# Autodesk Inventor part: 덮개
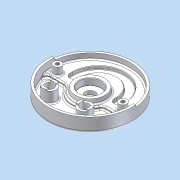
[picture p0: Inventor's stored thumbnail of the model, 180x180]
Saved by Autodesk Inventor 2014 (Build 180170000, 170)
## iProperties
Company: 한국ATC센터
Created: 2015-04
Part Number: 덮개
Document SubType Name: Modeling
Designer: KYOUNG IL JANG
Density: 2.71 g/cm^3
Material: 알루미늄-6061
Appearance: 매끄러움 - 흰색
Author: KYOUNG IL JANG
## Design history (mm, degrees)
sketch "스케치1"
  geometry: L1 (-59, -19)-(-59, 19); L2 (59, 19)-(59, -19); L3 (-41, 19)-(-41, -19); L4 (41, -19)-(41, 19); L5 (59, 5)-(41, 5); L6 (-41, 5)-(-59, 5); C1 r 90 at (0, 0); C2 r 95 at (0, 0); A1 r 59 centre (0, 19) between (59, 19) and (-59, 19); A2 r 59 centre (0, -19) between (-59, -19) and (59, -19); A3 r 41 centre (0, -19) between (-41, -19) and (41, -19); A4 r 41 centre (0, 19) between (41, 19) and (-41, 19); 2 further points
  constraints: 12 end point, 8 point on circle, 6 centre point, 4 point on line, 4 tangent, 2 parallel, 2 perpendicular, 1 coincident, 1 collinear, 1 horizontal alignment, 1 midpoint, 1 vertical, 1 vertical alignment, 3 other
  dimensions: "d2" = 180 diameter of C1; "d3" = 156 dimension on A2 A1; "d4" = 118 distance between parallel lines of L2 L1; "d5" = 18 distance between parallel lines of L2 L4; "d8" = 190 diameter of C2; "d121" = 5 distance from line of L5 point (0, 0)
extrude "돌출1" new body sketch "스케치1" distance "d6" = 14; taper "d7" = 0 deg
extrude "돌출2" join sketch "스케치1" distance "d9" = 13; taper "d10" = 0 deg
extrude "돌출3" cut sketch "스케치1" distance "d11" = 7; taper "d12" = 0 deg
sketch "스케치2"
  geometry: C1 r 11.5 at (0, 0); 1 further point
  constraints: 1 centre point, 1 coincident
  dimensions: "d13" = 23 diameter of C1
extrude "돌출4" cut sketch "스케치2" stored distance "d14" = 7; taper "d15" = 0 deg
fillet "모깎기1"
fillet "모깎기2"
sketch "스케치3"
  geometry: L1 (-89.658, 7.844)-(-94.638, 8.28); L2 (89.658, 7.844)-(94.638, 8.28); L3 (0, 0)-(0, -90); A1 r 95 centre (0, 0) between (-94.638, 8.28) and (94.638, 8.28) reference; A2 r 90 centre (0, 0) between (-89.658, 7.844) and (89.658, 7.844) reference; 1 further point
  constraints: 6 end point, 5 point on circle, 1 point on line, 1 vertical, 1 other
  dimensions: "d16" = 190 deg dimension on L2 L1
extrude "돌출5" join sketch "스케치3" distance "d17" = 5; taper "d18" = 0 deg
hole "구멍1" diameter "d21" = 50; stored, may be unused: countersink angle "d25" = 90 deg, drill point angle "d27" = 0 deg; dims "d19" = 10, "d20" = 10, "d22" = 6, "d23" = 4, "d24" = 2, "d26" = 5
fillet "모깎기3" dims "d28" = 0.3
fillet "모깎기5" dims "d30" = 3
sketch "스케치4"
  geometry: C1 r 35 at (0, 0); C2 r 25 at (0, 0); 1 further point
  constraints: 2 centre point, 1 coincident
  dimensions: "d32" = 70 diameter of C1 (derived); "d36" = 10 radial gap between concentric circles of C1 C2
extrude "돌출6" join sketch "스케치4" distance "d33" = 10; taper "d34" = 0 deg
feature "면 기울기2" dims angle "d37" = 10 deg
chamfer "모따기1" distance "d39" = 1; stored, may be unused: second distance "d40" = 2, angle "d41" = 45 deg
fillet "모깎기7" dims "d42" = 5
sketch "스케치5"
  geometry: L1 (-40.249, -12)-(-89.196, -12); L2 (40.249, -12)-(89.196, -12); A1 r 90 centre (0, 0) between (-89.196, -12) and (89.196, -12) reference; A2 r 42 centre (0, 0) between (-40.249, -12) and (40.249, -12); 1 further point
  constraints: 4 end point, 4 point on circle, 1 centre point, 1 collinear, 1 horizontal, 1 point on line
  dimensions: "d43" = 48 radial gap between concentric circles of A1 A2; "d44" = 12 distance from line of point (0, 0) L1
extrude "돌출7" cut sketch "스케치5" stored distance "d45" = 10; taper "d46" = 0 deg
fillet "모깎기8" dims "d47" = 10
chamfer "모따기2" distance "d49" = 1; stored, may be unused: second distance "d50" = 2, angle "d51" = 45 deg
sketch "스케치8"
  geometry: C1 r 9 at (74, 0); C2 r 9 at (-74, 0); A1 r 74 centre (0, 0) between (74, 0) and (-74, 0); 1 further point
  constraints: 3 centre point, 2 horizontal alignment, 2 point on circle, 1 coincident, 1 equal radius
  dimensions: "d64" = 18 diameter of C1; "d65" = 148 diameter of A1
extrude "돌출9" join sketch "스케치8" stored distance "d66" = 5; taper "d67" = 0 deg
sketch "스케치11"
  geometry: C1 r 15 at (40, -52); C2 r 15 at (-40, -52); 1 further point
  constraints: 2 centre point, 1 equal radius, 1 horizontal alignment
  dimensions: "d82" = 52 vertical distance of point (0, 0) C1.centre; "d83" = 30 diameter of C1; "d84" = 80 distance of C2.centre C1.centre; "d85" = 40 horizontal distance of point (0, 0) C1.centre (= 0.5 x d84)
extrude "돌출10" join sketch "스케치11" stored distance "d86" = 10; taper "d87" = 0 deg
node "구멍3"
node "구멍5"
hole "구멍6" diameter "d92" = 20; stored, may be unused: countersink angle "d96" = 90 deg, drill point angle "d98" = 118 deg; dims "d90" = 10, "d91" = 10, "d93" = 6, "d94" = 4, "d95" = 2, "d97" = 8
hole "구멍7" diameter "d101" = 20; stored, may be unused: countersink angle "d105" = 90 deg, drill point angle "d107" = 118 deg; dims "d99" = 10, "d100" = 10, "d102" = 6, "d103" = 4, "d104" = 2, "d106" = 8
fillet "모깎기13" dims "d108" = 3
sketch "스케치13"
  geometry: L1 (-20.252, -58)-(-26, -58); L2 (-42, -58)-(-47.748, -58); L3 (-20.252, -46)-(-26, -46); L4 (-42, -46)-(-47.748, -46); L5 (-108, -65.748)-(-108, -60); L6 (-108, -44)-(-108, -38.252); L7 (-120, -44)-(-120, -38.252); L8 (-120, -60)-(-120, -65.748); A1 r 15 centre (-34, -52) between (-20.252, -58) and (-47.748, -58) reference; A2 r 10 centre (-34, -52) between (-26, -58) and (-42, -58) reference; A3 r 15 centre (-114, -52) between (-108, -65.748) and (-108, -38.252) reference; A4 r 10 centre (-114, -52) between (-108, -60) and (-108, -44) reference; 1 further point
  constraints: 16 end point, 16 point on circle, 3 equal length, 3 point on line, 2 collinear, 1 horizontal, 1 perpendicular
  dimensions: "d114" = 12 distance between parallel lines of L4 L2; "d115" = 6 distance from line of A1.centre L2 (= 0.5 x d114); "d116" = 12 distance between parallel lines of L8 L5 (= d114); "d117" = 6 distance from line of A3.centre L5 (= d115)
extrude "돌출12" join sketch "스케치13" distance "d118" = 3; taper "d119" = 0 deg
fillet "모깎기14" dims "d120" = 1
node "솔리드1"
sketch "스케치9"
  geometry: 1 further point
hole "구멍2" sketch "스케치9" diameter "d68" = 8.376; stored, may be unused: countersink angle "d72" = 90 deg, drill point angle "d74" = 120 deg; dims "d69" = 16, "d70" = 4, "d71" = 2, "d73" = 21
sketch "스케치10"
  geometry: 1 further point
hole "구멍4" sketch "스케치10" diameter "d75" = 8.376; stored, may be unused: countersink angle "d79" = 90 deg, drill point angle "d81" = 120 deg; dims "d76" = 16, "d77" = 4, "d78" = 2, "d80" = 21
